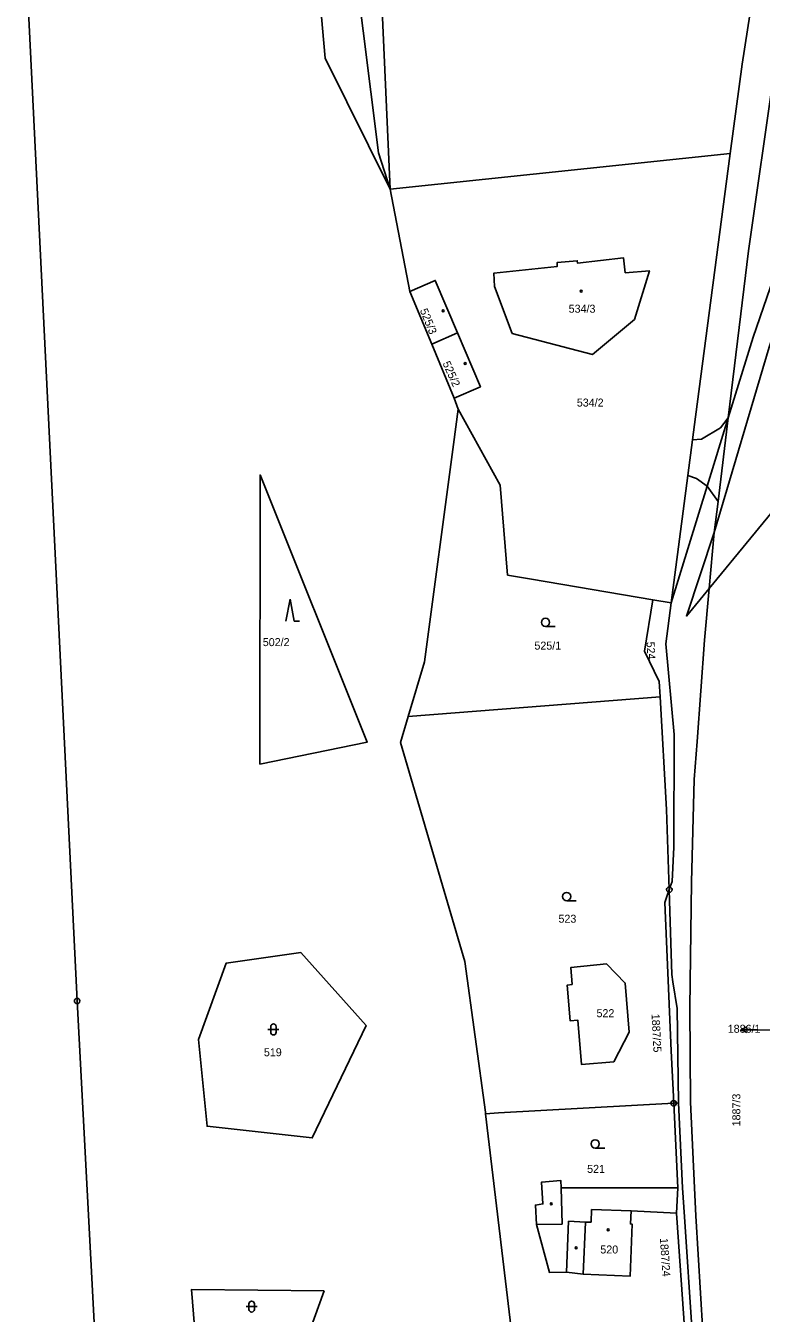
# Model space of a CAD drawing. Extents: x -587171 to -555306, y -1167727 to -1074732.
# Drawn here: x -561220.4 to -561086.2, y -1077893.1 to -1077658.3 of the extents above; entities that cross this region are included whole.
import ezdxf

# ---------------------------------------------------------------- set-up
doc = ezdxf.new("R2010")
doc.units = 0
for name, color, linetype in [('Hranice parcel', 7, 'Continuous'), ('Parcelní čísla', 7, 'Continuous'), ('Pop  PČ popisy', 7, 'Continuous'), ('Vnitřní kresba', 7, 'Continuous'), ('Značky bodu BP', 7, 'Continuous'), ('Značky budov', 7, 'Continuous'), ('Značky kultur', 7, 'Continuous')]:
    doc.layers.add(name, color=color, linetype=linetype)

msp = doc.modelspace()

# ---------------------------------------------------------------- linework, layer by layer
at = {"layer": 'Hranice parcel'}
for p, q in [((-561091.86, -1077681.63), (-561153.95, -1077688.11)), ((-561153.95, -1077688.11), (-561150.33, -1077706.77)), ((-561150.33, -1077706.77), (-561146.34, -1077716.35)), ((-561141.66, -1077714.32), (-561146.34, -1077716.35)), ((-561146.34, -1077716.35), (-561142.26, -1077726.2)), ((-561142.26, -1077726.2), (-561141.54, -1077728.25)), ((-561106, -1077763), (-561107.52, -1077772.4)), ((-561102.66, -1077763.58), (-561106, -1077763)), ((-561107.52, -1077772.4), (-561104.82, -1077777.91)), ((-561104.82, -1077777.91), (-561104.66, -1077780.73)), ((-561104.66, -1077780.73), (-561150.63, -1077784.31)), ((-561103.51, -1077801.25), (-561104.66, -1077780.73)), ((-561103, -1077815.87), (-561103.51, -1077801.25)), ((-561136.51, -1077856.73), (-561131.52, -1077898.6)), ((-561101.32, -1077854.78), (-561102.19, -1077854.83)), ((-561101.43, -1077870.25), (-561102.19, -1077854.83)), ((-561101.71, -1077874.89), (-561101.43, -1077870.25)), ((-561100.13, -1077896.67), (-561101.71, -1077874.89))]:
    msp.add_line(p, q, dxfattribs=at)
for points in [[(-561091.86, -1077681.63), (-561089.7, -1077665.29), (-561074.75, -1077568.98), (-561063.6, -1077534.48), (-561053.67, -1077503.25)], [(-561158.21, -1077592.83), (-561153.95, -1077688.11), (-561156.07, -1077681.46), (-561168.8, -1077580.32), (-561161.05, -1077552.79)], [(-561188.09, -1077581.05), (-561173, -1077584), (-561169.61, -1077621), (-561165.8, -1077664.2), (-561153.95, -1077688.11)], [(-561163.6, -1078030.63), (-561206.73, -1077917.78), (-561211.07, -1077836.17), (-561220.44, -1077645.75)], [(-561102.66, -1077763.58), (-561096.09, -1077742.27), (-561092.24, -1077729.79), (-561087.7, -1077715.09), (-561077.67, -1077686), (-561069.95, -1077664.47)], [(-561102.66, -1077763.58), (-561099.6, -1077740.32), (-561098.74, -1077733.82), (-561098.19, -1077729.63), (-561091.86, -1077681.63)], [(-561080.53, -1077742.45), (-561095.72, -1077760.94), (-561099.86, -1077765.98), (-561094.78, -1077750.73), (-561084.8, -1077716.93), (-561075.8, -1077690.78), (-561074.51, -1077692.91)], [(-561131.68, -1077714.43), (-561134.87, -1077705.87), (-561135.04, -1077703.44), (-561123.43, -1077702.21), (-561123.45, -1077701.48), (-561119.79, -1077701.15), (-561119.76, -1077701.59), (-561111.37, -1077700.61), (-561111.02, -1077703.34), (-561106.62, -1077702.98), (-561109.33, -1077711.85), (-561117.04, -1077718.25), (-561131.68, -1077714.43)], [(-561141.66, -1077714.32), (-561145.7, -1077704.74), (-561150.33, -1077706.77)], [(-561142.26, -1077726.2), (-561137.45, -1077724.15), (-561140.27, -1077717.61), (-561141.66, -1077714.32)], [(-561141.54, -1077728.25), (-561142.39, -1077734.7), (-561147.65, -1077774.3), (-561150.63, -1077784.31)], [(-561106, -1077763), (-561128.16, -1077759.23), (-561132.5, -1077758.5), (-561133.86, -1077742.1), (-561141.54, -1077728.25)], [(-561177.7, -1077792.98), (-561177.67, -1077740.22), (-561158.13, -1077788.95), (-561177.7, -1077792.98)], [(-561103, -1077815.87), (-561102.49, -1077814.41), (-561102.17, -1077808.15), (-561102.12, -1077787.55), (-561103.64, -1077771.02), (-561102.66, -1077763.58)], [(-561150.63, -1077784.31), (-561152.03, -1077789.03), (-561140.28, -1077828.97), (-561136.54, -1077856.48), (-561136.51, -1077856.73)], [(-561102.19, -1077854.83), (-561102.66, -1077845.25), (-561103.81, -1077818.2), (-561103, -1077815.87)], [(-561101.32, -1077854.78), (-561101.55, -1077837.52), (-561102.34, -1077832.68), (-561102.56, -1077831.36), (-561102.93, -1077817.92), (-561103, -1077815.87)], [(-561170.23, -1077827.32), (-561183.86, -1077829.26), (-561188.9, -1077843.23), (-561187.36, -1077859.02), (-561168.16, -1077861.16), (-561158.33, -1077840.62), (-561170.23, -1077827.32)], [(-561120.73, -1077833.19), (-561121.62, -1077833.26), (-561121.09, -1077839.78), (-561119.7, -1077839.67), (-561119.04, -1077847.75), (-561113.13, -1077847.25), (-561110.34, -1077841.89), (-561111.04, -1077832.9), (-561114.48, -1077829.39), (-561120.98, -1077830.07), (-561120.73, -1077833.19)], [(-561102.19, -1077854.83), (-561134.15, -1077856.59), (-561136.51, -1077856.73)], [(-561098.83, -1077896.59), (-561100.21, -1077875.53), (-561100.56, -1077870.25), (-561101.32, -1077854.78)], [(-561101.43, -1077870.25), (-561122.72, -1077870.23), (-561122.76, -1077868.93), (-561126.31, -1077869.22), (-561126.06, -1077873.19), (-561127.44, -1077873.39), (-561127.26, -1077876.94), (-561124.84, -1077885.71), (-561121.75, -1077885.65), (-561118.69, -1077886.02), (-561110.13, -1077886.35), (-561109.79, -1077876.86), (-561110.08, -1077876.85), (-561109.96, -1077874.46), (-561101.71, -1077874.89)], [(-561165.95, -1077889.02), (-561190.2, -1077888.81), (-561189.47, -1077897.8), (-561169.61, -1077899.11), (-561165.95, -1077889.02)]]:
    msp.add_lwpolyline(points, dxfattribs=at)
at = {"layer": 'Pop  PČ popisy'}
for p, q in [((-561089.85, -1077841.41), (-561088.84, -1077840.92)), ((-561086.85, -1077841.46), (-561089.85, -1077841.41)), ((-561089.85, -1077841.41), (-561088.86, -1077841.93)), ((-561084.46, -1077841.49), (-561086.85, -1077841.46))]:
    msp.add_line(p, q, dxfattribs=at)
at = {"layer": 'Vnitřní kresba'}
for p, q in [((-561094.09, -1077745.06), (-561092.24, -1077729.79)), ((-561092.24, -1077729.79), (-561093.65, -1077731.62)), ((-561099.6, -1077740.32), (-561098.01, -1077740.87)), ((-561098.01, -1077740.87), (-561096.09, -1077742.27)), ((-561096.09, -1077742.27), (-561094.09, -1077745.06)), ((-561094.78, -1077750.73), (-561094.09, -1077745.06)), ((-561095.72, -1077760.94), (-561094.78, -1077750.73)), ((-561096.59, -1077770.36), (-561095.72, -1077760.94)), ((-561097.93, -1077788.82), (-561096.59, -1077770.36)), ((-561098.44, -1077795.77), (-561097.93, -1077788.82)), ((-561098.96, -1077814.48), (-561098.44, -1077795.77)), ((-561099.12, -1077854.64), (-561099.24, -1077837.45)), ((-561122.53, -1077876.9), (-561122.72, -1077870.23)), ((-561117.18, -1077874.22), (-561117.28, -1077876.53)), ((-561109.96, -1077874.46), (-561117.18, -1077874.22)), ((-561096.89, -1077896.52), (-561098.14, -1077875.39)), ((-561127.26, -1077876.94), (-561122.53, -1077876.9)), ((-561121.37, -1077876.35), (-561121.75, -1077885.65)), ((-561118.28, -1077876.49), (-561121.37, -1077876.35)), ((-561118.69, -1077886.02), (-561118.28, -1077876.49)), ((-561117.28, -1077876.53), (-561118.28, -1077876.49))]:
    msp.add_line(p, q, dxfattribs=at)
for points in [[(-561092.24, -1077729.79), (-561088.54, -1077699.33), (-561083.87, -1077666.65), (-561079.03, -1077638.29)], [(-561098.74, -1077733.82), (-561097.1, -1077733.69), (-561093.65, -1077731.62)], [(-561099.24, -1077837.45), (-561099.18, -1077832.77), (-561098.96, -1077814.48)], [(-561098.14, -1077875.39), (-561098.38, -1077870.24), (-561099.12, -1077854.64)]]:
    msp.add_lwpolyline(points, dxfattribs=at)
at = {"layer": 'Značky bodu BP'}
for centre, radius in [((-561103, -1077815.87), 0.5), ((-561103, -1077815.87), 0.0303), ((-561211.07, -1077836.17), 0.5), ((-561211.07, -1077836.17), 0.0303), ((-561102.19, -1077854.83), 0.5), ((-561102.19, -1077854.83), 0.0303)]:
    msp.add_circle(centre, radius, dxfattribs=at)
at = {"layer": 'Značky budov'}
for centre in [(-561119.06, -1077706.69), (-561144.28, -1077710.29), (-561140.24, -1077719.91), (-561124.53, -1077873.16), (-561114.15, -1077877.91), (-561120, -1077881.18)]:
    msp.add_circle(centre, 0.175, dxfattribs=at)
at = {"layer": 'Značky kultur'}
for p, q in [((-561172.2, -1077762.9), (-561172.95, -1077766.9)), ((-561171.45, -1077766.9), (-561172.2, -1077762.9)), ((-561171.45, -1077766.9), (-561170.45, -1077766.9)), ((-561125.59, -1077767.87), (-561123.84, -1077767.87)), ((-561121.72, -1077817.88), (-561119.97, -1077817.88)), ((-561176.23, -1077841.36), (-561174.23, -1077841.36)), ((-561175.73, -1077840.86), (-561175.73, -1077841.86)), ((-561174.73, -1077841.86), (-561174.73, -1077840.86)), ((-561116.53, -1077862.99), (-561114.78, -1077862.99)), ((-561180.21, -1077891.92), (-561178.21, -1077891.92)), ((-561179.71, -1077891.42), (-561179.71, -1077892.42)), ((-561178.71, -1077892.42), (-561178.71, -1077891.42))]:
    msp.add_line(p, q, dxfattribs=at)
for centre in [(-561125.59, -1077767.12), (-561121.72, -1077817.13), (-561116.53, -1077862.24)]:
    msp.add_circle(centre, 0.75, dxfattribs=at)
for centre, start, end in [((-561175.23, -1077840.86), 0, 180), ((-561175.23, -1077841.86), 180, 359.9879), ((-561179.21, -1077891.42), 0, 180), ((-561179.21, -1077892.42), 180, 359.9879)]:
    msp.add_arc(centre, 0.5, start, end, dxfattribs=at)

# ---------------------------------------------------------------- texts
at = {"layer": 'Parcelní čísla'}
for s, rotation, p in [('525/3', 292, (-561148.54, -1077710.21)), ('525/2', 294, (-561144.41, -1077719.86)), ('524', 273, (-561107.15, -1077770.67)), ('1887/25', 273, (-561106.24, -1077838.54)), ('1887/3', 90, (-561090.03, -1077859.05)), ('1887/24', 274, (-561104.71, -1077879.46))]:
    msp.add_text(s, height=1.46, rotation=rotation, dxfattribs=at).set_placement(p)
for s, p in [('534/3', (-561121.36, -1077710.64)), ('534/2', (-561119.87, -1077727.76)), ('502/2', (-561177.18, -1077771.45)), ('525/1', (-561127.61, -1077772.09)), ('523', (-561123.22, -1077821.9)), ('522', (-561116.28, -1077839.13)), ('1886/1', (-561092.33, -1077841.97)), ('519', (-561176.98, -1077846.26)), ('521', (-561117.99, -1077867.53)), ('520', (-561115.58, -1077882.23))]:
    msp.add_text(s, height=1.46, dxfattribs=at).set_placement(p)

doc.saveas('drawing.dxf')
